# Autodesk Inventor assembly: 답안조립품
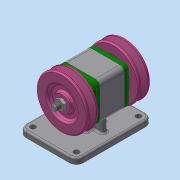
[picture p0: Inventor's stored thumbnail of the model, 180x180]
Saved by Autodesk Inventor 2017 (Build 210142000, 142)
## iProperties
Part Number: 답안조립품
Material: 일반
Document SubType Name: Assembly
Designer: 222
Author: 222
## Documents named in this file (10)
- C:\Users\222\Desktop\701106V1036\답안조립품.iam
- C:\Users\222\Desktop\701106V1036\본체.ipt
- C:\Users\222\Desktop\701106V1036\베어링 6004.ipt
- C:\Users\222\Desktop\701106V1036\축.ipt
- C:\Users\222\Desktop\701106V1036\커버.ipt
- C:\Users\222\Desktop\701106V1036\볼트 M4.ipt
- C:\Users\222\Desktop\701106V1036\오일 실 17 30 5.ipt
- C:\Users\222\Desktop\701106V1036\키 5 x 5 x 12.ipt
- C:\Users\222\Desktop\701106V1036\V-벨트풀리.ipt
- C:\Users\222\Desktop\701106V1036\너트 M10x1.ipt
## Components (2 placed, 1 different names)
1. V-벨트풀리:1
2. V-벨트풀리:2
